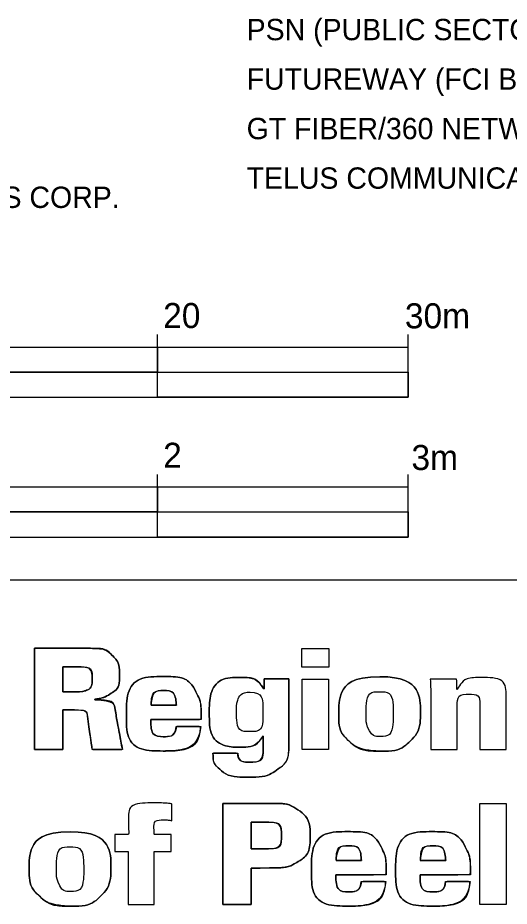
# Model space of a CAD drawing. Extents: x 613360 to 613780, y 4825621 to 4825911.
# Drawn here: x 613737.07 to 613756.68, y 4825658.5 to 4825693.95 of the extents above; entities that cross this region are included whole.
import ezdxf

# ---------------------------------------------------------------- set-up
doc = ezdxf.new("R2010")
doc.units = 0
for name, color, linetype in [('G-ANNO-BAR', 7, 'Continuous'), ('G-ANNO-TEXT', 7, 'Continuous'), ('G-TTLB-LOGO', 7, 'Continuous'), ('G-TTLB-OTLN', 7, 'Continuous')]:
    doc.layers.add(name, color=color, linetype=linetype)

msp = doc.modelspace()

# ---------------------------------------------------------------- linework, layer by layer
at = {"layer": 'G-ANNO-BAR'}
for p, q in [((613742.645, 4825678.805), (613742.645, 4825681.305)), ((613752.645, 4825678.805), (613752.645, 4825681.305)), ((613712.645, 4825680.805), (613752.645, 4825680.805)), ((613712.645, 4825679.805), (613752.645, 4825679.805)), ((613712.645, 4825678.805), (613752.645, 4825678.805)), ((613742.646, 4825673.229), (613742.646, 4825675.729)), ((613752.646, 4825673.229), (613752.646, 4825675.729)), ((613712.646, 4825675.229), (613752.646, 4825675.229)), ((613712.646, 4825674.229), (613752.646, 4825674.229)), ((613712.646, 4825673.229), (613752.646, 4825673.229))]:
    msp.add_line(p, q, dxfattribs=at)
for points in [[(613732.645, 4825680.805), (613742.645, 4825680.805), (613742.645, 4825679.805), (613732.645, 4825679.805)], [(613742.645, 4825679.805), (613752.645, 4825679.805), (613752.645, 4825678.805), (613742.645, 4825678.805)], [(613732.646, 4825675.229), (613742.646, 4825675.229), (613742.646, 4825674.229), (613732.646, 4825674.229)], [(613742.646, 4825674.229), (613752.646, 4825674.229), (613752.646, 4825673.229), (613742.646, 4825673.229)]]:
    msp.add_lwpolyline(points, close=True, dxfattribs=at)
at = {"layer": 'G-TTLB-LOGO'}
for p, q in [((613748.408, 4825668.781), (613749.482, 4825668.781)), ((613748.408, 4825668.032), (613748.408, 4825668.781)), ((613749.482, 4825668.781), (613749.482, 4825668.032)), ((613749.482, 4825668.032), (613748.408, 4825668.032)), ((613748.419, 4825667.562), (613749.47, 4825667.562)), ((613748.419, 4825664.754), (613748.419, 4825667.562)), ((613749.47, 4825667.562), (613749.47, 4825664.754)), ((613740.143, 4825666.762), (613740.143, 4825666.74)), ((613742.387, 4825666.516), (613743.399, 4825666.516)), ((613744.389, 4825665.946), (613742.375, 4825665.946)), ((613743.393, 4825665.672), (613744.372, 4825665.672)), ((613746.865, 4825664.928), (613746.865, 4825665.297)), ((613741.251, 4825664.754), (613740.037, 4825664.754)), ((613744.857, 4825664.604), (613745.847, 4825664.604)), ((613749.47, 4825664.754), (613748.419, 4825664.754)), ((613755.504, 4825662.605), (613756.556, 4825662.605)), ((613755.504, 4825658.567), (613755.504, 4825662.605)), ((613756.556, 4825662.605), (613756.556, 4825658.567)), ((613749.77, 4825660.329), (613750.782, 4825660.329)), ((613753.132, 4825660.329), (613754.144, 4825660.329)), ((613751.772, 4825659.758), (613749.759, 4825659.758)), ((613755.134, 4825659.758), (613753.12, 4825659.758)), ((613750.777, 4825659.484), (613751.756, 4825659.484)), ((613754.138, 4825659.484), (613755.117, 4825659.484)), ((613756.556, 4825658.567), (613755.504, 4825658.567))]:
    msp.add_line(p, q, dxfattribs=at)
for points in [[(613739.332, 4825666.332), (613738.862, 4825666.332), (613738.862, 4825664.754), (613737.738, 4825664.754), (613737.738, 4825668.792), (613739.606, 4825668.792)], [(613748.408, 4825668.781), (613749.482, 4825668.781), (613749.482, 4825668.032), (613748.408, 4825668.032), (613748.408, 4825668.781)], [(613739.282, 4825668.049), (613738.862, 4825668.049), (613738.862, 4825667.059), (613739.282, 4825667.059)], [(613746.899, 4825667.154), (613746.899, 4825667.579), (613747.889, 4825667.579), (613747.889, 4825664.961)], [(613748.419, 4825667.562), (613749.47, 4825667.562), (613749.47, 4825664.754), (613748.419, 4825664.754), (613748.419, 4825667.562)], [(613747.108, 4825660.027), (613746.381, 4825660.021), (613746.381, 4825658.567), (613745.257, 4825658.567), (613745.257, 4825662.605), (613747.113, 4825662.605)], [(613755.504, 4825662.605), (613756.556, 4825662.605), (613756.556, 4825658.567), (613755.504, 4825658.567), (613755.504, 4825662.605)], [(613746.873, 4825661.855), (613746.381, 4825661.855), (613746.381, 4825660.793), (613746.878, 4825660.793)]]:
    msp.add_lwpolyline(points, dxfattribs=at)
for points in [[(613737.738, 4825668.792), (613737.738, 4825668.792), (613739.606, 4825668.792), (613739.606, 4825668.792), (613740.333, 4825668.792), (613740.607, 4825668.748), (613740.848, 4825668.502), (613740.971, 4825668.378), (613741.127, 4825668.155), (613741.127, 4825667.719), (613741.127, 4825667.277), (613740.949, 4825667.086), (613740.758, 4825666.969), (613740.501, 4825666.807), (613740.255, 4825666.779), (613740.143, 4825666.762), (613740.143, 4825666.762), (613740.143, 4825666.74), (613740.143, 4825666.74), (613740.926, 4825666.717), (613740.942, 4825666.373), (613741.06, 4825665.75), (613741.112, 4825665.478), (613741.202, 4825664.949), (613741.251, 4825664.754), (613741.251, 4825664.754), (613740.037, 4825664.754), (613740.037, 4825664.754), (613740.017, 4825664.897), (613739.96, 4825665.318), (613739.913, 4825665.628), (613739.84, 4825666.112), (613739.836, 4825666.332), (613739.332, 4825666.332), (613739.332, 4825666.332), (613738.862, 4825666.332), (613738.862, 4825666.332), (613738.862, 4825666.332), (613738.862, 4825664.754), (613738.862, 4825664.754), (613738.862, 4825664.754), (613737.738, 4825664.754), (613737.738, 4825664.754), (613737.738, 4825664.754), (613737.738, 4825668.792), (613737.738, 4825668.792)], [(613739.606, 4825668.792), (613740.333, 4825668.792), (613740.607, 4825668.748), (613740.848, 4825668.502), (613740.971, 4825668.378), (613741.127, 4825668.155), (613741.127, 4825667.719), (613741.127, 4825667.277), (613740.949, 4825667.086), (613740.758, 4825666.969), (613740.501, 4825666.807), (613740.255, 4825666.779), (613740.143, 4825666.762)], [(613738.862, 4825667.059), (613738.862, 4825667.059), (613739.282, 4825667.059), (613739.282, 4825667.059), (613739.528, 4825667.059), (613739.651, 4825667.059), (613739.746, 4825667.092), (613739.992, 4825667.17), (613740.043, 4825667.422), (613740.043, 4825667.551), (613740.043, 4825668.049), (613739.606, 4825668.049), (613739.282, 4825668.049), (613739.282, 4825668.049), (613738.862, 4825668.049), (613738.862, 4825668.049), (613738.862, 4825668.049), (613738.862, 4825667.059), (613738.862, 4825667.059)], [(613739.282, 4825667.059), (613739.528, 4825667.059), (613739.651, 4825667.059), (613739.746, 4825667.092), (613739.992, 4825667.17), (613740.043, 4825667.422), (613740.043, 4825667.551), (613740.043, 4825668.049), (613739.606, 4825668.049), (613739.282, 4825668.049)], [(613742.375, 4825665.946), (613742.375, 4825665.794), (613742.375, 4825665.263), (613742.912, 4825665.263), (613743.192, 4825665.263), (613743.365, 4825665.409), (613743.393, 4825665.672), (613743.393, 4825665.672), (613744.372, 4825665.672), (613744.372, 4825665.672), (613744.294, 4825664.967), (613743.634, 4825664.693), (613742.907, 4825664.693), (613741.928, 4825664.693), (613741.402, 4825665.185), (613741.402, 4825666.114), (613741.402, 4825667.053), (613741.861, 4825667.663), (613742.896, 4825667.663), (613743.678, 4825667.663), (613744.042, 4825667.344), (613744.232, 4825666.947), (613744.355, 4825666.706), (613744.389, 4825666.438), (613744.389, 4825665.946), (613744.389, 4825665.946), (613742.375, 4825665.946), (613742.375, 4825665.946)], [(613744.372, 4825665.672), (613744.294, 4825664.967), (613743.634, 4825664.693), (613742.907, 4825664.693), (613741.928, 4825664.693), (613741.402, 4825665.185), (613741.402, 4825666.114), (613741.402, 4825667.053), (613741.861, 4825667.663), (613742.896, 4825667.663), (613743.678, 4825667.663), (613744.042, 4825667.344), (613744.232, 4825666.947), (613744.355, 4825666.706), (613744.389, 4825666.438), (613744.389, 4825665.946)], [(613747.889, 4825667.579), (613747.889, 4825667.579), (613747.889, 4825664.961), (613747.889, 4825664.961), (613747.889, 4825664.626), (613747.822, 4825664.229), (613747.441, 4825663.96), (613747.201, 4825663.787), (613746.86, 4825663.647), (613746.284, 4825663.647), (613745.965, 4825663.647), (613745.433, 4825663.692), (613745.115, 4825663.977), (613744.869, 4825664.195), (613744.863, 4825664.458), (613744.857, 4825664.604), (613744.857, 4825664.604), (613745.847, 4825664.604), (613745.847, 4825664.604), (613745.853, 4825664.391), (613746.004, 4825664.245), (613746.306, 4825664.245), (613746.832, 4825664.245), (613746.865, 4825664.626), (613746.865, 4825664.928), (613746.865, 4825664.928), (613746.865, 4825665.297), (613746.865, 4825665.297), (613746.58, 4825664.872), (613746.121, 4825664.844), (613745.959, 4825664.844), (613745.366, 4825664.844), (613744.712, 4825665.213), (613744.712, 4825666.236), (613744.712, 4825666.997), (613745.115, 4825667.629), (613745.97, 4825667.629), (613746.513, 4825667.629), (613746.759, 4825667.377), (613746.899, 4825667.154), (613746.899, 4825667.154), (613746.899, 4825667.579), (613746.899, 4825667.579), (613746.899, 4825667.579), (613747.889, 4825667.579), (613747.889, 4825667.579)], [(613746.865, 4825665.297), (613746.58, 4825664.872), (613746.121, 4825664.844), (613745.959, 4825664.844), (613745.366, 4825664.844), (613744.712, 4825665.213), (613744.712, 4825666.236), (613744.712, 4825666.997), (613745.115, 4825667.629), (613745.97, 4825667.629), (613746.513, 4825667.629), (613746.759, 4825667.377), (613746.899, 4825667.154)], [(613751.518, 4825667.657), (613752.43, 4825667.657), (613753.14, 4825667.198), (613753.14, 4825666.203), (613753.14, 4825665.794), (613753.023, 4825665.381), (613752.732, 4825665.09), (613752.497, 4825664.861), (613752.15, 4825664.687), (613751.574, 4825664.687), (613750.953, 4825664.687), (613750.551, 4825664.838), (613750.277, 4825665.101), (613749.952, 4825665.409), (613749.874, 4825665.828), (613749.874, 4825666.169), (613749.874, 4825667.031), (613750.405, 4825667.657), (613751.518, 4825667.657)], [(613751.218, 4825664.706), (613750.793, 4825664.754), (613750.495, 4825664.892), (613750.277, 4825665.101), (613749.952, 4825665.409), (613749.874, 4825665.828), (613749.874, 4825666.169), (613749.874, 4825667.031), (613750.405, 4825667.657), (613751.518, 4825667.657)], [(613751.518, 4825667.657), (613752.43, 4825667.657), (613753.14, 4825667.198), (613753.14, 4825666.203), (613753.14, 4825665.794), (613753.023, 4825665.381), (613752.732, 4825665.09), (613752.497, 4825664.861), (613752.15, 4825664.687), (613751.574, 4825664.687), (613751.447, 4825664.687), (613751.328, 4825664.694), (613751.218, 4825664.706)], [(613753.558, 4825666.964), (613753.558, 4825666.964), (613753.53, 4825667.562), (613753.53, 4825667.562), (613753.53, 4825667.562), (613754.581, 4825667.562), (613754.581, 4825667.562), (613754.581, 4825667.562), (613754.593, 4825667.131), (613754.593, 4825667.131), (613754.721, 4825667.344), (613754.945, 4825667.623), (613755.527, 4825667.623), (613756.556, 4825667.623), (613756.556, 4825666.841), (613756.556, 4825666.454), (613756.556, 4825666.454), (613756.556, 4825664.754), (613756.556, 4825664.754), (613756.556, 4825664.754), (613755.504, 4825664.754), (613755.504, 4825664.754), (613755.504, 4825664.754), (613755.504, 4825666.365), (613755.504, 4825666.365), (613755.504, 4825666.561), (613755.504, 4825666.958), (613755.074, 4825666.958), (613754.604, 4825666.958), (613754.604, 4825666.466), (613754.604, 4825666.365), (613754.604, 4825666.365), (613754.604, 4825664.754), (613754.604, 4825664.754), (613754.604, 4825664.754), (613753.558, 4825664.754), (613753.558, 4825664.754), (613753.558, 4825664.754), (613753.558, 4825666.964), (613753.558, 4825666.964)], [(613753.558, 4825666.964), (613753.558, 4825666.964), (613753.53, 4825667.562), (613753.53, 4825667.562), (613753.53, 4825667.562), (613754.581, 4825667.562), (613754.581, 4825667.562), (613754.581, 4825667.562), (613754.593, 4825667.131), (613754.593, 4825667.131), (613754.721, 4825667.344), (613754.945, 4825667.623), (613755.527, 4825667.623), (613756.556, 4825667.623), (613756.556, 4825666.841), (613756.556, 4825666.454), (613756.556, 4825666.454), (613756.556, 4825664.754), (613756.556, 4825664.754), (613756.556, 4825664.754), (613755.504, 4825664.754), (613755.504, 4825664.754), (613755.504, 4825664.754), (613755.504, 4825666.365), (613755.504, 4825666.365), (613755.504, 4825666.561), (613755.504, 4825666.958), (613755.074, 4825666.958), (613754.604, 4825666.958), (613754.604, 4825666.466), (613754.604, 4825666.365), (613754.604, 4825666.365), (613754.604, 4825664.754), (613754.604, 4825664.754), (613754.604, 4825664.754), (613753.558, 4825664.754), (613753.558, 4825664.754), (613753.558, 4825664.754), (613753.558, 4825666.964), (613753.558, 4825666.964)], [(613743.399, 4825666.516), (613743.388, 4825666.678), (613743.354, 4825667.103), (613742.896, 4825667.103), (613742.437, 4825667.103), (613742.398, 4825666.65), (613742.387, 4825666.516), (613742.387, 4825666.516), (613743.399, 4825666.516), (613743.399, 4825666.516)], [(613743.399, 4825666.516), (613743.388, 4825666.678), (613743.354, 4825667.103), (613742.896, 4825667.103), (613742.437, 4825667.103), (613742.398, 4825666.65), (613742.387, 4825666.516)], [(613746.339, 4825667.042), (613745.987, 4825667.042), (613745.797, 4825666.717), (613745.797, 4825666.248), (613745.797, 4825665.951), (613745.864, 4825665.465), (613746.328, 4825665.465), (613746.832, 4825665.465), (613746.849, 4825666.057), (613746.849, 4825666.259), (613746.849, 4825666.404), (613746.849, 4825667.042), (613746.339, 4825667.042)], [(613746.339, 4825667.042), (613745.987, 4825667.042), (613745.797, 4825666.717), (613745.797, 4825666.248), (613745.797, 4825665.951), (613745.864, 4825665.465), (613746.328, 4825665.465), (613746.832, 4825665.465), (613746.849, 4825666.057), (613746.849, 4825666.259), (613746.849, 4825666.404), (613746.849, 4825667.042), (613746.339, 4825667.042)], [(613751.099, 4825665.498), (613751.222, 4825665.286), (613751.412, 4825665.275), (613751.507, 4825665.275), (613751.966, 4825665.275), (613752.055, 4825665.772), (613752.055, 4825666.164), (613752.055, 4825666.65), (613751.938, 4825667.059), (613751.518, 4825667.059), (613751.054, 4825667.059), (613750.965, 4825666.583), (613750.965, 4825666.164), (613750.965, 4825665.979), (613750.981, 4825665.705), (613751.099, 4825665.498)], [(613751.099, 4825665.498), (613751.222, 4825665.286), (613751.412, 4825665.275), (613751.507, 4825665.275), (613751.966, 4825665.275), (613752.055, 4825665.772), (613752.055, 4825666.164), (613752.055, 4825666.65), (613751.938, 4825667.059), (613751.518, 4825667.059), (613751.054, 4825667.059), (613750.965, 4825666.583), (613750.965, 4825666.164), (613750.965, 4825665.979), (613750.981, 4825665.705), (613751.099, 4825665.498)], [(613740.143, 4825666.74), (613740.926, 4825666.717), (613740.942, 4825666.373), (613741.06, 4825665.75), (613741.112, 4825665.478), (613741.202, 4825664.949), (613741.251, 4825664.754)], [(613740.037, 4825664.754), (613740.017, 4825664.897), (613739.96, 4825665.318), (613739.913, 4825665.628), (613739.84, 4825666.112), (613739.836, 4825666.332), (613739.332, 4825666.332)], [(613742.375, 4825665.946), (613742.375, 4825665.794), (613742.375, 4825665.263), (613742.912, 4825665.263), (613743.192, 4825665.263), (613743.365, 4825665.409), (613743.393, 4825665.672)], [(613747.889, 4825664.961), (613747.889, 4825664.626), (613747.822, 4825664.229), (613747.441, 4825663.96), (613747.201, 4825663.787), (613746.86, 4825663.647), (613746.284, 4825663.647), (613745.965, 4825663.647), (613745.433, 4825663.692), (613745.115, 4825663.977), (613744.869, 4825664.195), (613744.863, 4825664.458), (613744.857, 4825664.604)], [(613745.847, 4825664.604), (613745.853, 4825664.391), (613746.004, 4825664.245), (613746.306, 4825664.245), (613746.832, 4825664.245), (613746.865, 4825664.626), (613746.865, 4825664.928)], [(613743.215, 4825661.911), (613743.17, 4825661.923), (613743.064, 4825661.945), (613742.924, 4825661.945), (613742.493, 4825661.945), (613742.505, 4825661.598), (613742.51, 4825661.363), (613742.51, 4825661.363), (613743.187, 4825661.363), (613743.187, 4825661.363), (613743.187, 4825661.363), (613743.187, 4825660.681), (613743.187, 4825660.681), (613743.187, 4825660.681), (613742.51, 4825660.681), (613742.51, 4825660.681), (613742.51, 4825660.681), (613742.51, 4825658.567), (613742.51, 4825658.567), (613742.51, 4825658.567), (613741.481, 4825658.567), (613741.481, 4825658.567), (613741.481, 4825658.567), (613741.481, 4825660.681), (613741.481, 4825660.681), (613741.481, 4825660.681), (613740.939, 4825660.681), (613740.939, 4825660.681), (613740.939, 4825660.681), (613740.939, 4825661.363), (613740.939, 4825661.363), (613740.939, 4825661.363), (613741.498, 4825661.363), (613741.498, 4825661.363), (613741.481, 4825662.034), (613741.493, 4825662.622), (613742.594, 4825662.622), (613742.88, 4825662.622), (613743.098, 4825662.599), (613743.215, 4825662.588), (613743.215, 4825662.588), (613743.215, 4825661.911), (613743.215, 4825661.911)], [(613743.215, 4825661.911), (613743.17, 4825661.923), (613743.064, 4825661.945), (613742.924, 4825661.945), (613742.493, 4825661.945), (613742.505, 4825661.598), (613742.51, 4825661.363), (613742.51, 4825661.363), (613743.187, 4825661.363), (613743.187, 4825661.363), (613743.187, 4825661.363), (613743.187, 4825660.681), (613743.187, 4825660.681), (613743.187, 4825660.681), (613742.51, 4825660.681), (613742.51, 4825660.681), (613742.51, 4825660.681), (613742.51, 4825658.567), (613742.51, 4825658.567), (613742.51, 4825658.567), (613741.481, 4825658.567), (613741.481, 4825658.567), (613741.481, 4825658.567), (613741.481, 4825660.681), (613741.481, 4825660.681), (613741.481, 4825660.681), (613740.939, 4825660.681), (613740.939, 4825660.681), (613740.939, 4825660.681), (613740.939, 4825661.363), (613740.939, 4825661.363), (613740.939, 4825661.363), (613741.498, 4825661.363), (613741.498, 4825661.363), (613741.481, 4825662.034), (613741.493, 4825662.622), (613742.594, 4825662.622), (613742.88, 4825662.622), (613743.098, 4825662.599), (613743.215, 4825662.588), (613743.215, 4825662.588), (613743.215, 4825661.911), (613743.215, 4825661.911)], [(613745.257, 4825662.605), (613745.257, 4825662.605), (613747.113, 4825662.605), (613747.113, 4825662.605), (613747.427, 4825662.605), (613747.835, 4825662.605), (613748.165, 4825662.398), (613748.506, 4825662.191), (613748.735, 4825661.828), (613748.735, 4825661.302), (613748.735, 4825660.592), (613748.282, 4825660.284), (613748.126, 4825660.2), (613747.812, 4825660.027), (613747.326, 4825660.027), (613747.108, 4825660.027), (613747.108, 4825660.027), (613746.381, 4825660.021), (613746.381, 4825660.021), (613746.381, 4825660.021), (613746.381, 4825658.567), (613746.381, 4825658.567), (613746.381, 4825658.567), (613745.257, 4825658.567), (613745.257, 4825658.567), (613745.257, 4825658.567), (613745.257, 4825662.605), (613745.257, 4825662.605)], [(613747.113, 4825662.605), (613747.427, 4825662.605), (613747.835, 4825662.605), (613748.165, 4825662.398), (613748.506, 4825662.191), (613748.735, 4825661.828), (613748.735, 4825661.302), (613748.735, 4825660.592), (613748.282, 4825660.284), (613748.126, 4825660.2), (613747.812, 4825660.027), (613747.326, 4825660.027), (613747.108, 4825660.027)], [(613746.381, 4825660.793), (613746.381, 4825660.793), (613746.878, 4825660.793), (613746.878, 4825660.793), (613747.153, 4825660.793), (613747.594, 4825660.793), (613747.594, 4825661.335), (613747.594, 4825661.828), (613747.197, 4825661.855), (613746.873, 4825661.855), (613746.873, 4825661.855), (613746.381, 4825661.855), (613746.381, 4825661.855), (613746.381, 4825661.855), (613746.381, 4825660.793), (613746.381, 4825660.793)], [(613746.878, 4825660.793), (613747.153, 4825660.793), (613747.594, 4825660.793), (613747.594, 4825661.335), (613747.594, 4825661.828), (613747.197, 4825661.855), (613746.873, 4825661.855)], [(613739.164, 4825661.469), (613740.076, 4825661.469), (613740.786, 4825661.011), (613740.786, 4825660.016), (613740.786, 4825659.607), (613740.669, 4825659.193), (613740.378, 4825658.902), (613740.143, 4825658.673), (613739.796, 4825658.5), (613739.22, 4825658.5), (613738.6, 4825658.5), (613738.197, 4825658.651), (613737.923, 4825658.914), (613737.598, 4825659.221), (613737.52, 4825659.641), (613737.52, 4825659.982), (613737.52, 4825660.843), (613738.051, 4825661.469), (613739.164, 4825661.469)], [(613738.865, 4825658.519), (613738.44, 4825658.567), (613738.141, 4825658.705), (613737.923, 4825658.914), (613737.598, 4825659.221), (613737.52, 4825659.641), (613737.52, 4825659.982), (613737.52, 4825660.843), (613738.051, 4825661.469), (613739.164, 4825661.469)], [(613739.164, 4825661.469), (613740.076, 4825661.469), (613740.786, 4825661.011), (613740.786, 4825660.016), (613740.786, 4825659.607), (613740.669, 4825659.193), (613740.378, 4825658.902), (613740.143, 4825658.673), (613739.796, 4825658.5), (613739.22, 4825658.5), (613739.093, 4825658.5), (613738.975, 4825658.506), (613738.865, 4825658.519)], [(613749.759, 4825659.758), (613749.759, 4825659.607), (613749.759, 4825659.076), (613750.296, 4825659.076), (613750.575, 4825659.076), (613750.749, 4825659.221), (613750.777, 4825659.484), (613750.777, 4825659.484), (613751.756, 4825659.484), (613751.756, 4825659.484), (613751.677, 4825658.779), (613751.017, 4825658.505), (613750.29, 4825658.505), (613749.311, 4825658.505), (613748.786, 4825658.998), (613748.786, 4825659.926), (613748.786, 4825660.865), (613749.244, 4825661.475), (613750.279, 4825661.475), (613751.062, 4825661.475), (613751.426, 4825661.156), (613751.616, 4825660.759), (613751.739, 4825660.519), (613751.772, 4825660.25), (613751.772, 4825659.758), (613751.772, 4825659.758), (613749.759, 4825659.758), (613749.759, 4825659.758)], [(613751.756, 4825659.484), (613751.677, 4825658.779), (613751.017, 4825658.505), (613750.29, 4825658.505), (613749.311, 4825658.505), (613748.786, 4825658.998), (613748.786, 4825659.926), (613748.786, 4825660.865), (613749.244, 4825661.475), (613750.279, 4825661.475), (613751.062, 4825661.475), (613751.426, 4825661.156), (613751.616, 4825660.759), (613751.739, 4825660.519), (613751.772, 4825660.25), (613751.772, 4825659.758)], [(613753.12, 4825659.758), (613753.12, 4825659.607), (613753.12, 4825659.076), (613753.657, 4825659.076), (613753.937, 4825659.076), (613754.11, 4825659.221), (613754.138, 4825659.484), (613754.138, 4825659.484), (613755.117, 4825659.484), (613755.117, 4825659.484), (613755.039, 4825658.779), (613754.379, 4825658.505), (613753.652, 4825658.505), (613752.673, 4825658.505), (613752.147, 4825658.998), (613752.147, 4825659.926), (613752.147, 4825660.865), (613752.606, 4825661.475), (613753.641, 4825661.475), (613754.424, 4825661.475), (613754.787, 4825661.156), (613754.977, 4825660.759), (613755.1, 4825660.519), (613755.134, 4825660.25), (613755.134, 4825659.758), (613755.134, 4825659.758), (613753.12, 4825659.758), (613753.12, 4825659.758)], [(613755.117, 4825659.484), (613755.039, 4825658.779), (613754.379, 4825658.505), (613753.652, 4825658.505), (613752.673, 4825658.505), (613752.147, 4825658.998), (613752.147, 4825659.926), (613752.147, 4825660.865), (613752.606, 4825661.475), (613753.641, 4825661.475), (613754.424, 4825661.475), (613754.787, 4825661.156), (613754.977, 4825660.759), (613755.1, 4825660.519), (613755.134, 4825660.25), (613755.134, 4825659.758)], [(613738.745, 4825659.311), (613738.868, 4825659.098), (613739.058, 4825659.087), (613739.153, 4825659.087), (613739.612, 4825659.087), (613739.701, 4825659.585), (613739.701, 4825659.976), (613739.701, 4825660.463), (613739.584, 4825660.871), (613739.164, 4825660.871), (613738.7, 4825660.871), (613738.611, 4825660.396), (613738.611, 4825659.976), (613738.611, 4825659.792), (613738.627, 4825659.518), (613738.745, 4825659.311)], [(613738.745, 4825659.311), (613738.868, 4825659.098), (613739.058, 4825659.087), (613739.153, 4825659.087), (613739.612, 4825659.087), (613739.701, 4825659.585), (613739.701, 4825659.976), (613739.701, 4825660.463), (613739.584, 4825660.871), (613739.164, 4825660.871), (613738.7, 4825660.871), (613738.611, 4825660.396), (613738.611, 4825659.976), (613738.611, 4825659.792), (613738.627, 4825659.518), (613738.745, 4825659.311)], [(613750.782, 4825660.329), (613750.771, 4825660.491), (613750.738, 4825660.916), (613750.279, 4825660.916), (613749.821, 4825660.916), (613749.781, 4825660.463), (613749.77, 4825660.329), (613749.77, 4825660.329), (613750.782, 4825660.329), (613750.782, 4825660.329)], [(613750.782, 4825660.329), (613750.771, 4825660.491), (613750.738, 4825660.916), (613750.279, 4825660.916), (613749.821, 4825660.916), (613749.781, 4825660.463), (613749.77, 4825660.329)], [(613754.144, 4825660.329), (613754.133, 4825660.491), (613754.099, 4825660.916), (613753.641, 4825660.916), (613753.182, 4825660.916), (613753.143, 4825660.463), (613753.132, 4825660.329), (613753.132, 4825660.329), (613754.144, 4825660.329), (613754.144, 4825660.329)], [(613754.144, 4825660.329), (613754.133, 4825660.491), (613754.099, 4825660.916), (613753.641, 4825660.916), (613753.182, 4825660.916), (613753.143, 4825660.463), (613753.132, 4825660.329)], [(613749.759, 4825659.758), (613749.759, 4825659.607), (613749.759, 4825659.076), (613750.296, 4825659.076), (613750.575, 4825659.076), (613750.749, 4825659.221), (613750.777, 4825659.484)], [(613753.12, 4825659.758), (613753.12, 4825659.607), (613753.12, 4825659.076), (613753.657, 4825659.076), (613753.937, 4825659.076), (613754.11, 4825659.221), (613754.138, 4825659.484)]]:
    msp.add_open_spline(points, degree=3, dxfattribs=at)
at = {"layer": 'G-TTLB-OTLN'}
msp.add_line((613774.178, 4825671.507), (613710.777, 4825671.507), dxfattribs=at)

# ---------------------------------------------------------------- texts
at = {"layer": 'G-ANNO-BAR'}
for s, p in [('20', (613742.871, 4825681.567)), ('30m', (613752.516, 4825681.556)), ('2', (613742.872, 4825675.991)), ('3m', (613752.778, 4825675.903))]:
    msp.add_text(s, height=1, rotation=360, dxfattribs=at).set_placement(p)
at = {"layer": 'G-ANNO-TEXT'}
for s, p in [('PSN (PUBLIC SECTOR NETWORK)', (613746.202, 4825693.052)), ('FUTUREWAY (FCI BROADBAND)', (613746.202, 4825691.077)), ('GT FIBER/360 NETWORK INC.', (613746.202, 4825689.102)), ('TELUS COMMUNICATION', (613746.202, 4825687.127)), ('PEARSON INTERNATIONAL FUEL FACILITIES CORP.', (613712.651, 4825686.36))]:
    msp.add_text(s, height=0.85, dxfattribs=at).set_placement(p)

doc.saveas('drawing.dxf')
